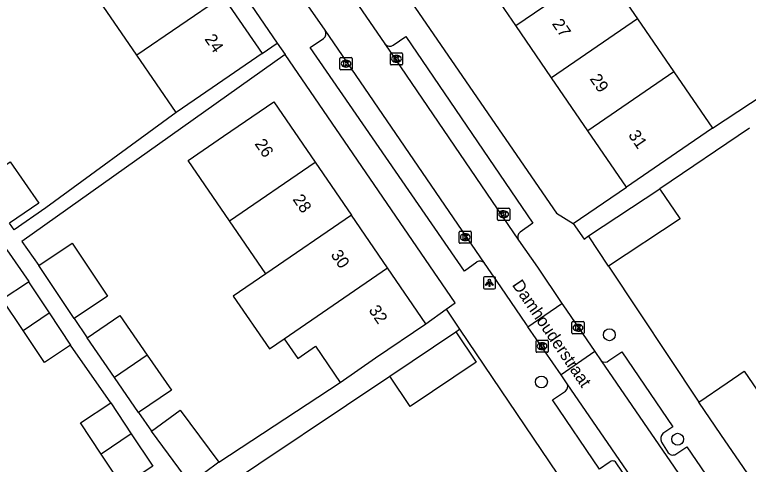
# Model space of a CAD drawing. Extents: x 157466 to 158888, y 383063 to 384677.
# Drawn here: x 158217.2 to 158277.7, y 383459 to 383496 of the extents above; entities that cross this region are included whole.
import ezdxf

# ---------------------------------------------------------------- set-up
doc = ezdxf.new("R2010")
doc.units = 0
for name, color, linetype in [('IMGEO_Boom', 7, 'Continuous'), ('IMGEO_Kolk', 7, 'Continuous'), ('IMGEO_Lichtpunt', 7, 'Continuous'), ('IMGEO_Openbare_ruimte_label', 7, 'Continuous'), ('IMGEO_Pand', 7, 'Continuous'), ('IMGEO_Pand_nummerreeks', 7, 'Continuous'), ('IMGEO_Rijbaan_lokaal_open', 7, 'Continuous'), ('IMGEO_Voetpad_open', 7, 'Continuous')]:
    doc.layers.add(name, color=color, linetype=linetype)

msp = doc.modelspace()

# ---------------------------------------------------------------- linework, layer by layer
at = {"layer": 'IMGEO_Boom'}
for centre in [(158266.215, 383469.641), (158260.617, 383465.752), (158271.842, 383461.025)]:
    msp.add_circle(centre, 0.489, dxfattribs=at)
at = {"layer": 'IMGEO_Kolk'}
for p, q in [((158248.244, 383492.892), (158249.096, 383492.892)), ((158244.013, 383491.574), (158244.013, 383492.426)), ((158244.088, 383492.5), (158244.94, 383492.5)), ((158244.501, 383492.28), (158244.526, 383492.28)), ((158245.014, 383492.426), (158245.014, 383491.574)), ((158248.169, 383491.966), (158248.169, 383492.818)), ((158248.657, 383492.672), (158248.682, 383492.672)), ((158249.17, 383492.818), (158249.17, 383491.966)), ((158244.524, 383491.72), (158244.499, 383491.72)), ((158249.096, 383491.892), (158248.244, 383491.892)), ((158248.68, 383492.112), (158248.655, 383492.112)), ((158244.94, 383491.5), (158244.088, 383491.5)), ((158257.001, 383479.152), (158257.001, 383480.004)), ((158257.076, 383480.078), (158257.928, 383480.078)), ((158257.489, 383479.858), (158257.514, 383479.858)), ((158258.002, 383480.004), (158258.002, 383479.152)), ((158257.928, 383479.078), (158257.076, 383479.078)), ((158257.512, 383479.298), (158257.487, 383479.298)), ((158253.833, 383477.261), (158253.833, 383478.113)), ((158253.908, 383478.187), (158254.76, 383478.187)), ((158254.321, 383477.967), (158254.346, 383477.967)), ((158254.834, 383478.113), (158254.834, 383477.261)), ((158254.76, 383477.187), (158253.908, 383477.187)), ((158254.344, 383477.407), (158254.319, 383477.407)), ((158263.131, 383469.796), (158263.131, 383470.648)), ((158263.206, 383470.722), (158264.058, 383470.722)), ((158263.619, 383470.502), (158263.644, 383470.502)), ((158264.132, 383470.648), (158264.132, 383469.796)), ((158263.642, 383469.942), (158263.617, 383469.942)), ((158264.058, 383469.722), (158263.206, 383469.722)), ((158260.17, 383468.27), (158260.17, 383469.122)), ((158260.245, 383469.196), (158261.097, 383469.196)), ((158260.658, 383468.976), (158260.683, 383468.976)), ((158261.171, 383469.122), (158261.171, 383468.27)), ((158261.097, 383468.196), (158260.245, 383468.196)), ((158260.681, 383468.416), (158260.656, 383468.416))]:
    msp.add_line(p, q, dxfattribs=at)
for points in [[(158248.244, 383492.892), (158249.096, 383492.892)], [(158244.013, 383491.574), (158244.013, 383492.426)], [(158244.088, 383492.5), (158244.94, 383492.5)], [(158245.014, 383492.426), (158245.014, 383491.574)], [(158248.169, 383491.966), (158248.169, 383492.818)], [(158248.49, 383492.592), (158248.613, 383492.592), (158248.613, 383492.441), (158248.743, 383492.592), (158248.907, 383492.592), (158248.761, 383492.441), (158248.914, 383492.192), (158248.762, 383492.192), (158248.677, 383492.356), (158248.613, 383492.289), (158248.613, 383492.192), (158248.49, 383492.192), (158248.49, 383492.592)], [(158249.17, 383492.818), (158249.17, 383491.966)], [(158244.334, 383492.2), (158244.457, 383492.2), (158244.457, 383492.049), (158244.587, 383492.2), (158244.751, 383492.2), (158244.605, 383492.049), (158244.758, 383491.8), (158244.606, 383491.8), (158244.521, 383491.964), (158244.457, 383491.897), (158244.457, 383491.8), (158244.334, 383491.8), (158244.334, 383492.2)], [(158249.096, 383491.892), (158248.244, 383491.892)], [(158244.94, 383491.5), (158244.088, 383491.5)], [(158257.001, 383479.152), (158257.001, 383480.004)], [(158257.076, 383480.078), (158257.928, 383480.078)], [(158257.322, 383479.778), (158257.445, 383479.778), (158257.445, 383479.627), (158257.575, 383479.778), (158257.739, 383479.778), (158257.593, 383479.627), (158257.746, 383479.378), (158257.594, 383479.378), (158257.509, 383479.542), (158257.445, 383479.475), (158257.445, 383479.378), (158257.322, 383479.378), (158257.322, 383479.778)], [(158258.002, 383480.004), (158258.002, 383479.152)], [(158257.928, 383479.078), (158257.076, 383479.078)], [(158253.833, 383477.261), (158253.833, 383478.113)], [(158253.908, 383478.187), (158254.76, 383478.187)], [(158254.154, 383477.887), (158254.277, 383477.887), (158254.277, 383477.736), (158254.407, 383477.887), (158254.571, 383477.887), (158254.425, 383477.736), (158254.578, 383477.487), (158254.426, 383477.487), (158254.341, 383477.651), (158254.277, 383477.584), (158254.277, 383477.487), (158254.154, 383477.487), (158254.154, 383477.887)], [(158254.834, 383478.113), (158254.834, 383477.261)], [(158254.76, 383477.187), (158253.908, 383477.187)], [(158263.131, 383469.796), (158263.131, 383470.648)], [(158263.206, 383470.722), (158264.058, 383470.722)], [(158264.132, 383470.648), (158264.132, 383469.796)], [(158263.452, 383470.422), (158263.575, 383470.422), (158263.575, 383470.271), (158263.705, 383470.422), (158263.869, 383470.422), (158263.723, 383470.271), (158263.876, 383470.022), (158263.724, 383470.022), (158263.639, 383470.186), (158263.575, 383470.119), (158263.575, 383470.022), (158263.452, 383470.022), (158263.452, 383470.422)], [(158264.058, 383469.722), (158263.206, 383469.722)], [(158260.17, 383468.27), (158260.17, 383469.122)], [(158260.245, 383469.196), (158261.097, 383469.196)], [(158260.491, 383468.896), (158260.614, 383468.896), (158260.614, 383468.745), (158260.744, 383468.896), (158260.908, 383468.896), (158260.762, 383468.745), (158260.915, 383468.496), (158260.763, 383468.496), (158260.678, 383468.66), (158260.614, 383468.593), (158260.614, 383468.496), (158260.491, 383468.496), (158260.491, 383468.896)], [(158261.171, 383469.122), (158261.171, 383468.27)], [(158261.097, 383468.196), (158260.245, 383468.196)]]:
    msp.add_lwpolyline(points, dxfattribs=at)
for centre, start, end in [((158248.246, 383492.816), 91.55205, 178.44795), ((158248.246, 383492.816), 91.55205, 178.44795), ((158249.094, 383492.816), 1.55205, 88.44795), ((158249.094, 383492.816), 1.55205, 88.44795), ((158244.09, 383492.424), 91.55205, 178.44795), ((158244.09, 383492.424), 91.55205, 178.44795), ((158244.938, 383492.424), 1.55205, 88.44795), ((158244.938, 383492.424), 1.55205, 88.44795), ((158248.246, 383491.968), 181.55205, 268.44795), ((158248.246, 383491.968), 181.55205, 268.44795), ((158249.094, 383491.968), 271.55205, 358.44795), ((158249.094, 383491.968), 271.55205, 358.44795), ((158244.09, 383491.576), 181.55205, 268.44795), ((158244.09, 383491.576), 181.55205, 268.44795), ((158244.938, 383491.576), 271.55205, 358.44795), ((158244.938, 383491.576), 271.55205, 358.44795), ((158257.078, 383480.002), 91.55205, 178.44795), ((158257.078, 383480.002), 91.55205, 178.44795), ((158257.926, 383480.002), 1.55205, 88.44795), ((158257.926, 383480.002), 1.55205, 88.44795), ((158257.078, 383479.154), 181.55205, 268.44795), ((158257.078, 383479.154), 181.55205, 268.44795), ((158257.926, 383479.154), 271.55205, 358.44795), ((158257.926, 383479.154), 271.55205, 358.44795), ((158253.91, 383478.111), 91.55205, 178.44795), ((158253.91, 383478.111), 91.55205, 178.44795), ((158254.758, 383478.111), 1.55205, 88.44795), ((158254.758, 383478.111), 1.55205, 88.44795), ((158253.91, 383477.263), 181.55205, 268.44795), ((158253.91, 383477.263), 181.55205, 268.44795), ((158254.758, 383477.263), 271.55205, 358.44795), ((158254.758, 383477.263), 271.55205, 358.44795), ((158263.208, 383470.646), 91.55205, 178.44795), ((158263.208, 383470.646), 91.55205, 178.44795), ((158264.056, 383470.646), 1.55205, 88.44795), ((158264.056, 383470.646), 1.55205, 88.44795), ((158263.208, 383469.798), 181.55205, 268.44795), ((158263.208, 383469.798), 181.55205, 268.44795), ((158264.056, 383469.798), 271.55205, 358.44795), ((158264.056, 383469.798), 271.55205, 358.44795), ((158260.247, 383469.12), 91.55205, 178.44795), ((158260.247, 383469.12), 91.55205, 178.44795), ((158261.095, 383469.12), 1.55205, 88.44795), ((158261.095, 383469.12), 1.55205, 88.44795), ((158260.247, 383468.272), 181.55205, 268.44795), ((158260.247, 383468.272), 181.55205, 268.44795), ((158261.095, 383468.272), 271.55205, 358.44795), ((158261.095, 383468.272), 271.55205, 358.44795)]:
    msp.add_arc(centre, 0.0765, start, end, dxfattribs=at)
for centre, major_axis, ratio, start_param, end_param in [((158244.5, 383492), (-0.387, 0.002), 0.722429, 4.712389, 7.853982), ((158244.525, 383492), (-0.39, 0.002), 0.717154, 1.570796, 4.712389), ((158248.656, 383492.392), (-0.387, 0.002), 0.722429, 4.712389, 7.853982), ((158248.681, 383492.392), (-0.39, 0.002), 0.717154, 1.570796, 4.712389), ((158257.488, 383479.578), (-0.387, 0.002), 0.722429, 4.712389, 7.853982), ((158257.513, 383479.578), (-0.39, 0.002), 0.717154, 1.570796, 4.712389), ((158254.32, 383477.687), (-0.387, 0.002), 0.722429, 4.712389, 7.853982), ((158254.345, 383477.687), (-0.39, 0.002), 0.717154, 1.570796, 4.712389), ((158263.618, 383470.222), (-0.387, 0.002), 0.722429, 4.712389, 7.853982), ((158263.643, 383470.222), (-0.39, 0.002), 0.717154, 1.570796, 4.712389), ((158260.657, 383468.696), (-0.387, 0.002), 0.722429, 4.712389, 7.853982), ((158260.682, 383468.696), (-0.39, 0.002), 0.717154, 1.570796, 4.712389)]:
    msp.add_ellipse(centre, major_axis=major_axis, ratio=ratio, start_param=start_param, end_param=end_param, dxfattribs=at)
at = {"layer": 'IMGEO_Lichtpunt'}
for p, q in [((158255.83, 383474.331), (158255.83, 383473.524)), ((158255.83, 383474.331), (158255.83, 383473.524)), ((158256.732, 383474.426), (158255.924, 383474.426)), ((158256.732, 383474.426), (158255.924, 383474.426)), ((158256.826, 383473.524), (158256.826, 383474.331)), ((158256.826, 383473.524), (158256.826, 383474.331)), ((158255.924, 383473.43), (158256.732, 383473.43)), ((158255.924, 383473.43), (158256.732, 383473.43))]:
    msp.add_line(p, q, dxfattribs=at)
for points in [[(158256.204, 383473.995), (158256.243, 383473.967), (158256.055, 383473.705), (158256.017, 383473.732), (158256.204, 383473.995)], [(158256.306, 383473.947), (158256.353, 383473.947), (158256.353, 383473.625), (158256.306, 383473.625), (158256.306, 383473.947)], [(158256.416, 383473.967), (158256.454, 383473.994), (158256.641, 383473.732), (158256.602, 383473.704), (158256.416, 383473.967)]]:
    msp.add_lwpolyline(points, dxfattribs=at)
msp.add_circle((158256.329, 383474.129), 0.0994, dxfattribs=at)
for centre, start, end in [((158255.924, 383474.331), 90, 180), ((158255.924, 383474.331), 90, 180), ((158256.732, 383474.331), 0, 90), ((158256.732, 383474.331), 0, 90), ((158255.924, 383473.524), 180, 270), ((158255.924, 383473.524), 180, 270), ((158256.732, 383473.524), 270, 0), ((158256.732, 383473.524), 270, 360)]:
    msp.add_arc(centre, 0.0946, start, end, dxfattribs=at)
at = {"layer": 'IMGEO_Pand'}
for points in [[(158258.5, 383495.134), (158255.168, 383500), (158255.099, 383500.101), (158259.224, 383502.926), (158262.19, 383504.957), (158265.591, 383499.994)], [(158258.5, 383495.134), (158265.591, 383499.994)], [(158265.591, 383499.994), (158268.536, 383495.697)], [(158227.269, 383492.701), (158224.2, 383497.185)], [(158234.37, 383497.561), (158227.269, 383492.701)], [(158234.37, 383497.561), (158237.604, 383492.835)], [(158268.536, 383495.697), (158261.443, 383490.837)], [(158268.536, 383495.697), (158271.532, 383491.325)], [(158261.443, 383490.837), (158258.5, 383495.134)], [(158230.505, 383487.973), (158227.269, 383492.701)], [(158237.604, 383492.835), (158233.479, 383490.01), (158230.505, 383487.973)], [(158271.532, 383491.325), (158264.437, 383486.465)], [(158271.532, 383491.325), (158274.714, 383486.682)], [(158264.437, 383486.465), (158261.443, 383490.837)], [(158234.903, 383479.028), (158231.491, 383484.011), (158234.426, 383486.021), (158238.551, 383488.845), (158241.962, 383483.863)], [(158267.616, 383481.822), (158264.437, 383486.465)], [(158274.714, 383486.682), (158271.742, 383484.647), (158267.616, 383481.822)], [(158214.435, 383482.259), (158216.842, 383483.913), (158219.193, 383480.489), (158216.786, 383478.835)], [(158234.903, 383479.028), (158241.962, 383483.863)], [(158241.962, 383483.863), (158244.955, 383479.493)], [(158264.491, 383477.795), (158270.373, 383481.674)], [(158270.373, 383481.674), (158270.44, 383481.575), (158271.971, 383479.305), (158272.043, 383479.198), (158266.135, 383475.301)], [(158237.896, 383474.657), (158234.903, 383479.028)], [(158244.955, 383479.493), (158237.896, 383474.657)], [(158247.93, 383475.148), (158244.955, 383479.493)], [(158266.135, 383475.301), (158264.491, 383477.795)], [(158219.186, 383475.351), (158221.935, 383477.193), (158224.855, 383472.838), (158222.106, 383470.995)], [(158222.106, 383470.995), (158219.186, 383475.351)], [(158239.422, 383469.32), (158247.93, 383475.148)], [(158251.078, 383470.551), (158247.93, 383475.148)], [(158237.896, 383474.657), (158235.219, 383472.824), (158238.195, 383468.479), (158239.422, 383469.32)], [(158217.895, 383469.987), (158216.184, 383472.566), (158218.34, 383473.995)], [(158218.34, 383473.995), (158220.033, 383471.443)], [(158217.895, 383469.987), (158220.033, 383471.443)], [(158220.033, 383471.443), (158221.804, 383468.772)], [(158223.186, 383469.384), (158225.88, 383471.236), (158228.128, 383467.965)], [(158244.018, 383465.716), (158246.953, 383467.726), (158251.078, 383470.551)], [(158221.804, 383468.772), (158219.649, 383467.342), (158217.895, 383469.987)], [(158248.13, 383466.216), (158253.553, 383469.872)], [(158253.553, 383469.872), (158255.231, 383467.385), (158249.808, 383463.729), (158248.13, 383466.216)], [(158225.432, 383466.118), (158223.186, 383469.384)], [(158239.422, 383469.32), (158240.533, 383467.697), (158241.982, 383468.69), (158244.018, 383465.716)], [(158228.128, 383467.965), (158225.432, 383466.118)], [(158228.128, 383467.965), (158230.114, 383465.077), (158227.421, 383463.226)], [(158273.585, 383464.075), (158275.923, 383465.677), (158277.323, 383466.636), (158279.159, 383463.956), (158281.371, 383465.45), (158281.679, 383464.995), (158281.829, 383465.098)], [(158227.421, 383463.226), (158225.432, 383466.118)], [(158224.34, 383459.789), (158222.626, 383462.373), (158225.114, 383464.023)], [(158225.114, 383464.023), (158226.808, 383461.469)], [(158279.13, 383455.982), (158275.404, 383461.42), (158273.585, 383464.075)], [(158228.473, 383461.683), (158230.838, 383463.432), (158234.019, 383459.132)], [(158226.808, 383461.469), (158224.34, 383459.789)], [(158226.808, 383461.469), (158228.578, 383458.799)], [(158234.019, 383459.132), (158231.655, 383457.383), (158228.473, 383461.683)], [(158228.578, 383458.799), (158226.091, 383457.149), (158224.34, 383459.789)]]:
    msp.add_lwpolyline(points, dxfattribs=at)
at = {"layer": 'IMGEO_Rijbaan_lokaal_open'}
for points in [[(158244.094, 383498.921), (158245.53, 383496.782), (158247.722, 383493.631)], [(158242.783, 383494.759), (158241.2, 383497.039)], [(158255.919, 383475.538), (158242.783, 383494.759)], [(158247.722, 383493.631), (158258.728, 383477.438)], [(158258.728, 383477.438), (158260.287, 383475.203), (158262.287, 383472.225)], [(158259.507, 383470.303), (158259.373, 383470.5), (158257.256, 383473.597), (158255.919, 383475.538)], [(158259.507, 383470.303), (158262.287, 383472.225)], [(158262.287, 383472.225), (158262.372, 383472.098), (158265.006, 383468.252)], [(158262.238, 383466.339), (158259.507, 383470.303)], [(158265.006, 383468.252), (158262.238, 383466.339)], [(158265.006, 383468.252), (158265.526, 383467.504)], [(158265.526, 383467.504), (158276.3, 383451.789)], [(158262.733, 383465.598), (158262.238, 383466.339)], [(158273.468, 383449.96), (158262.733, 383465.598)]]:
    msp.add_lwpolyline(points, dxfattribs=at)
at = {"layer": 'IMGEO_Voetpad_open'}
for points in [[(158201.824, 383547.755), (158202.728, 383546.459), (158238.846, 383493.685)], [(158248.726, 383498.787), (158261.869, 383479.658), (158263.225, 383478.825)], [(158274.714, 383486.682), (158287.155, 383494.87)], [(158255.28, 383475.642), (158254.273, 383474.898), (158241.566, 383493.32), (158242.651, 383494.063)], [(158248.398, 383493.528), (158249.433, 383494.23), (158259.918, 383478.856), (158258.873, 383478.106)], [(158237.604, 383492.835), (158238.846, 383493.685)], [(158238.846, 383493.685), (158239.489, 383492.745)], [(158239.489, 383492.745), (158217.787, 383477.319), (158219.186, 383475.351)], [(158252.756, 383471.75), (158253.494, 383472.281), (158239.489, 383492.745)], [(158230.505, 383487.973), (158219.777, 383480.105), (158217.152, 383478.302), (158216.786, 383478.835)], [(158277.76, 383486.673), (158270.373, 383481.674)], [(158263.225, 383478.825), (158267.616, 383481.822)], [(158263.225, 383478.825), (158264.125, 383477.532), (158264.491, 383477.795)], [(158218.34, 383473.995), (158218.389, 383474.028), (158216.591, 383476.642), (158206.293, 383469.555)], [(158266.135, 383475.301), (158273.585, 383464.075)], [(158251.078, 383470.551), (158252.756, 383471.75)], [(158252.756, 383471.75), (158253.873, 383470.093)], [(158222.106, 383470.995), (158223.186, 383469.384)], [(158253.553, 383469.872), (158253.873, 383470.093)], [(158253.873, 383470.093), (158264.622, 383454.147), (158268.319, 383448.776), (158272.122, 383443.31)], [(158225.114, 383464.023), (158221.804, 383468.772)], [(158266.18, 383467.513), (158267.248, 383468.234), (158271.432, 383462.047), (158270.624, 383461.51)], [(158219.38, 383446.973), (158248.13, 383466.216)], [(158234.019, 383459.132), (158244.018, 383465.716)], [(158266.205, 383459.113), (158265.409, 383458.559), (158261.525, 383464.274), (158262.589, 383465.002)], [(158227.421, 383463.226), (158228.473, 383461.683)], [(158270.518, 383460.775), (158271.065, 383459.913)], [(158271.781, 383459.857), (158272.585, 383460.398), (158277.573, 383453.119), (158276.474, 383452.357)], [(158267.5, 383458.032), (158266.824, 383459.009)]]:
    msp.add_lwpolyline(points, dxfattribs=at)
for centre, radius, start, end in [((158242.332, 383494.484), 0.528, 307.16364, 31.35857), ((158248.112, 383493.923), 0.487, 216.77706, 305.89625), ((158259.141, 383477.698), 0.488, 123.27245, 212.23361), ((158255.54, 383475.225), 0.492, 39.5864, 121.92543), ((158265.848, 383467.857), 0.478, 227.57795, 313.9989), ((158262.32, 383465.382), 0.466, 305.22533, 27.60874), ((158271.03, 383461.076), 0.594, 133.11337, 210.47367), ((158271.448, 383460.205), 0.482, 217.35538, 313.70036), ((158266.482, 383458.866), 0.371, 22.63164, 138.29365)]:
    msp.add_arc(centre, radius, start, end, dxfattribs=at)

# ---------------------------------------------------------------- texts
at = {"layer": 'IMGEO_Openbare_ruimte_label'}
msp.add_text('Damhouderstraat', height=1, rotation=304.19864, dxfattribs=at).set_placement((158258.159, 383473.752))
at = {"layer": 'IMGEO_Pand_nummerreeks'}
for s, rotation, p in [('27', 304.40236, (158261.448, 383495.289)), ('24', 304.38382, (158232.815, 383494.028)), ('29', 304.40236, (158264.56, 383490.744)), ('31', 304.40236, (158267.736, 383486.107)), ('26', 304.40178, (158236.943, 383485.387)), ('28', 304.40178, (158240.077, 383480.811)), ('30', 304.40018, (158243.21, 383476.238)), ('32', 304.40018, (158246.337, 383471.669))]:
    msp.add_text(s, height=1, rotation=rotation, dxfattribs=at).set_placement(p)

doc.saveas('drawing.dxf')
